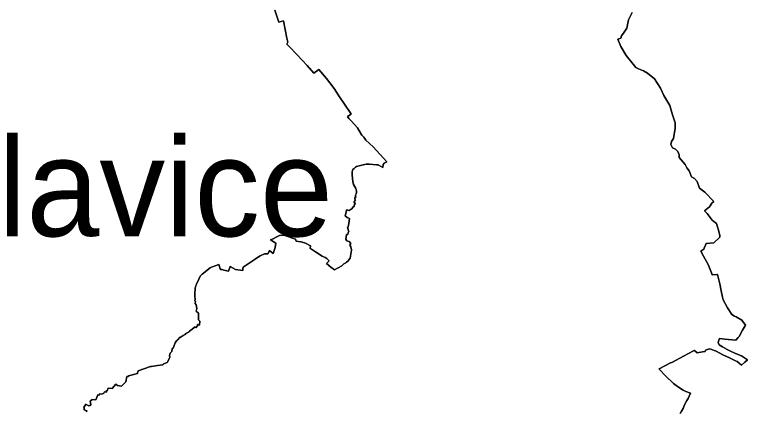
# Model space of a CAD drawing. Extents: x -742239 to -650174, y -1010569 to -945473.
# Drawn here: x -699245 to -695553, y -989972 to -987975 of the extents above; entities that cross this region are included whole.
import ezdxf

# ---------------------------------------------------------------- set-up
doc = ezdxf.new("R2010")
doc.units = 0
doc.layers.add('Hranice obcí', color=7, linetype='Continuous')
doc.layers.add('Obce popis', color=7, linetype='Continuous')

msp = doc.modelspace()

# ---------------------------------------------------------------- linework, layer by layer
at = {"layer": 'Hranice obcí'}
for points in [[(-697656, -988318.1), (-697673, -988296), (-697712.7, -988250.1), (-697736.3, -988270), (-697771.5, -988230), (-697796, -988204.3), (-697824.2, -988173.6), (-697857.1, -988139.3), (-697873.3, -988123.9), (-697868.9, -988113.7), (-697873.3, -988093.1), (-697890.4, -988005.7), (-697913.2, -988013), (-697917.6, -988002.1), (-697932.9, -987952.4)], [(-697932.9, -987952.4), (-697917.6, -988002.1), (-697913.2, -988013), (-697890.4, -988005.7), (-697873.3, -988093.1), (-697868.9, -988113.7), (-697873.3, -988123.9), (-697857.1, -988139.3), (-697824.2, -988173.6), (-697796, -988204.3), (-697771.5, -988230), (-697736.3, -988270), (-697712.7, -988250.1), (-697673, -988296), (-697656, -988318.1), (-697634.5, -988345.7), (-697611.1, -988384.2), (-697579.5, -988431.1), (-697554.7, -988467.7), (-697549.3, -988475), (-697566.8, -988488)], [(-695721.4, -989124.5), (-695692.1, -989094.4), (-695692.1, -989084.4), (-695695.8, -989068.6), (-695696.4, -989065.6), (-695704.5, -989037.3), (-695708.8, -989026.4), (-695721.4, -989016.3), (-695730.1, -989009), (-695754.6, -988975.8), (-695767.5, -988964), (-695768.3, -988963.1), (-695759.5, -988955.6), (-695743.6, -988941.9), (-695730.9, -988923.8), (-695721.3, -988915.3), (-695767.7, -988867.7), (-695793.4, -988849.2), (-695805.2, -988814.5), (-695819.4, -988798.9), (-695821.9, -988797.7), (-695833.8, -988791.6), (-695845.3, -988760.3), (-695858.3, -988745.5), (-695865.8, -988729.1), (-695896.4, -988693.9), (-695896.1, -988690.9), (-695896.8, -988679.7), (-695902.8, -988664.4), (-695914.5, -988652.8), (-695929.3, -988644.5), (-695938.4, -988629.2), (-695934.3, -988612.9), (-695924.1, -988598.2), (-695916.4, -988546), (-695916.5, -988518.9), (-695930.3, -988479), (-695943.7, -988432.1), (-695973.2, -988381.3), (-695989.6, -988345), (-696019.9, -988297.6), (-696055, -988270), (-696076, -988257.4), (-696101.4, -988247.4), (-696114.8, -988240.1), (-696128.7, -988224.4), (-696163.4, -988179.6), (-696189.7, -988135.3), (-696204.7, -988098.1), (-696190, -988093.3), (-696186, -988081.9), (-696172.6, -988062.6), (-696159.4, -988042.7), (-696152.3, -988000.5), (-696141.8, -987980.7), (-696132.8, -987964.4)], [(-696132.8, -987964.4), (-696141.8, -987980.7), (-696152.3, -988000.5), (-696159.4, -988042.7), (-696172.6, -988062.6), (-696186, -988081.9), (-696190, -988093.3), (-696204.7, -988098.1), (-696189.7, -988135.3), (-696163.4, -988179.6), (-696128.7, -988224.4), (-696114.8, -988240.1), (-696101.4, -988247.4), (-696076, -988257.4), (-696055, -988270), (-696019.9, -988297.6), (-695989.6, -988345), (-695973.2, -988381.3), (-695943.7, -988432.1), (-695930.3, -988479), (-695916.5, -988518.9), (-695916.4, -988546), (-695924.1, -988598.2), (-695934.3, -988612.9), (-695938.4, -988629.2), (-695929.3, -988644.5), (-695914.5, -988652.8), (-695902.8, -988664.4)], [(-697802.5, -989118.8), (-697800.6, -989118.9), (-697779.5, -989125.1), (-697753.7, -989138.1), (-697755.4, -989151.5), (-697749.4, -989156.4), (-697728.3, -989168.6), (-697694.4, -989190.3), (-697680.3, -989198.2), (-697671.6, -989202.9), (-697660.5, -989214.4), (-697673, -989227.8), (-697650.9, -989246.3), (-697632.3, -989259.6), (-697595.8, -989240), (-697593.2, -989235.4), (-697586.1, -989229), (-697576.5, -989224.8), (-697574.5, -989223.1), (-697572.2, -989221.3), (-697565.1, -989215.3), (-697554.4, -989201.2), (-697546.8, -989160.2), (-697547.2, -989158.3), (-697550.1, -989144.6), (-697556.4, -989135.8), (-697550.8, -989126.3), (-697558.4, -989116.6), (-697571.4, -989114.2), (-697575.1, -989105), (-697572.8, -989081), (-697566.1, -989081.2), (-697564, -989071.9), (-697561.3, -989068.7), (-697567.2, -989046.1), (-697564.3, -989045.5), (-697563.9, -989042.5), (-697561.5, -989026.2), (-697557.5, -989000.4), (-697569.6, -988996.7), (-697578.6, -988988), (-697573.2, -988962.4), (-697572.5, -988959.3), (-697572.2, -988958.2), (-697559.2, -988960.3), (-697549.5, -988954.4), (-697547.2, -988953.1), (-697545.4, -988952.3), (-697539.3, -988941.7), (-697533.3, -988939.9), (-697531.7, -988928.7), (-697527.8, -988926.1), (-697535, -988919.7), (-697527.9, -988908.8), (-697528.8, -988906.4), (-697529.9, -988901.9), (-697529.8, -988896.1), (-697526, -988896.1), (-697525.8, -988891.4), (-697527.2, -988891.1), (-697526.8, -988883.7), (-697524.4, -988877.4), (-697522.9, -988870.6), (-697522.7, -988864.3), (-697523.4, -988856.4), (-697525.2, -988850.8), (-697526.9, -988846.1), (-697537.2, -988830.7), (-697540.8, -988815.1), (-697544.2, -988782.4), (-697543.5, -988765.4), (-697542.5, -988759.6), (-697541, -988754), (-697534.6, -988748.7), (-697526.9, -988743.3), (-697521.4, -988739.5), (-697502.1, -988733.9), (-697494.8, -988732.3), (-697473, -988727.3), (-697457.4, -988726.9), (-697421.6, -988730.8), (-697412.5, -988731.7), (-697390.1, -988744.4), (-697387.8, -988729.9), (-697382.7, -988721.9), (-697369.9, -988716), (-697438, -988639.4), (-697475.7, -988606.7), (-697484.7, -988591), (-697495.2, -988582.1), (-697498.2, -988577), (-697517.3, -988544.8), (-697548.7, -988509.6), (-697560.7, -988496.7), (-697566.8, -988488), (-697549.3, -988475), (-697554.7, -988467.7), (-697579.5, -988431.1), (-697611.1, -988384.2), (-697634.5, -988345.7), (-697656, -988318.1)], [(-697566.8, -988488), (-697560.7, -988496.7), (-697548.7, -988509.6), (-697517.3, -988544.8), (-697498.2, -988577), (-697495.2, -988582.1), (-697484.7, -988591), (-697475.7, -988606.7), (-697438, -988639.4), (-697369.9, -988716), (-697382.7, -988721.9), (-697387.8, -988729.9), (-697390.1, -988744.4), (-697412.5, -988731.7), (-697421.6, -988730.8), (-697457.4, -988726.9), (-697473, -988727.3), (-697494.8, -988732.3), (-697502.1, -988733.9), (-697521.4, -988739.5), (-697526.9, -988743.3), (-697534.6, -988748.7), (-697541, -988754), (-697542.5, -988759.6), (-697543.5, -988765.4), (-697544.2, -988782.4), (-697540.8, -988815.1), (-697537.2, -988830.7), (-697526.9, -988846.1), (-697525.2, -988850.8), (-697523.4, -988856.4), (-697522.7, -988864.3), (-697522.9, -988870.6), (-697524.4, -988877.4), (-697526.8, -988883.7), (-697527.2, -988891.1), (-697525.8, -988891.4), (-697526, -988896.1), (-697529.8, -988896.1), (-697529.9, -988901.9), (-697528.8, -988906.4), (-697527.9, -988908.8), (-697535, -988919.7), (-697527.8, -988926.1), (-697531.7, -988928.7), (-697533.3, -988939.9), (-697539.3, -988941.7), (-697545.4, -988952.3), (-697547.2, -988953.1), (-697549.5, -988954.4), (-697559.2, -988960.3), (-697572.2, -988958.2), (-697572.5, -988959.3), (-697573.2, -988962.4), (-697578.6, -988988), (-697569.6, -988996.7), (-697557.5, -989000.4), (-697561.5, -989026.2), (-697563.9, -989042.5), (-697564.3, -989045.5), (-697567.2, -989046.1), (-697561.3, -989068.7), (-697564, -989071.9), (-697566.1, -989081.2), (-697572.8, -989081), (-697575.1, -989105), (-697571.4, -989114.2), (-697558.4, -989116.6), (-697550.8, -989126.3), (-697556.4, -989135.8), (-697550.1, -989144.6), (-697547.2, -989158.3), (-697546.8, -989160.2), (-697554.4, -989201.2), (-697565.1, -989215.3), (-697572.2, -989221.3), (-697574.5, -989223.1), (-697576.5, -989224.8), (-697586.1, -989229), (-697593.2, -989235.4), (-697595.8, -989240), (-697632.3, -989259.6), (-697650.9, -989246.3), (-697673, -989227.8), (-697660.5, -989214.4), (-697671.6, -989202.9), (-697680.3, -989198.2), (-697694.4, -989190.3), (-697728.3, -989168.6), (-697749.4, -989156.4), (-697755.4, -989151.5), (-697753.7, -989138.1), (-697779.5, -989125.1), (-697800.6, -989118.9), (-697802.5, -989118.8), (-697826.8, -989115.8), (-697829.2, -989105.6), (-697883.4, -989086.9), (-697889.1, -989085.1), (-697894.9, -989085.5), (-697910.2, -989086.6)], [(-695902.8, -988664.4), (-695896.8, -988679.7), (-695896.1, -988690.9), (-695896.4, -988693.9), (-695865.8, -988729.1), (-695858.3, -988745.5), (-695845.3, -988760.3), (-695833.8, -988791.6), (-695821.9, -988797.7), (-695819.4, -988798.9), (-695805.2, -988814.5), (-695793.4, -988849.2), (-695767.7, -988867.7), (-695721.3, -988915.3), (-695730.9, -988923.8), (-695743.6, -988941.9), (-695759.5, -988955.6), (-695768.3, -988963.1), (-695767.5, -988964), (-695754.6, -988975.8), (-695730.1, -989009), (-695721.4, -989016.3), (-695708.8, -989026.4), (-695704.5, -989037.3), (-695696.4, -989065.6), (-695695.8, -989068.6), (-695692.1, -989084.4), (-695692.1, -989094.4), (-695721.4, -989124.5), (-695760.7, -989127.6), (-695767.7, -989143.2), (-695768.8, -989146.3), (-695772.4, -989155.1), (-695787.7, -989165.9), (-695773.7, -989190.6), (-695749.3, -989232.9), (-695733.9, -989274.7), (-695729.6, -989284.4), (-695706.4, -989282.9), (-695702.4, -989282.4), (-695697.3, -989303.2), (-695691, -989330.7), (-695684.7, -989366), (-695677.9, -989396.7), (-695673.7, -989411.5), (-695653.4, -989451.8), (-695630.6, -989484.2), (-695616.6, -989492.3), (-695608.6, -989496.8), (-695580.3, -989513), (-695561.7, -989537.8), (-695576.7, -989564.3), (-695594.4, -989594.6), (-695597.5, -989598.8), (-695599.4, -989600.7), (-695610.1, -989614.2), (-695665.8, -989608.8), (-695693.6, -989606), (-695696.6, -989614.7), (-695700.3, -989625.4), (-695694.5, -989637.6), (-695678.4, -989647.2), (-695653.9, -989661), (-695641.4, -989667.5), (-695611.6, -989680.7), (-695582.2, -989693.5), (-695552.7, -989713.4), (-695566.1, -989724.9), (-695582.8, -989740), (-695603.3, -989720.8), (-695612.3, -989717.2), (-695629.1, -989709.1), (-695645.2, -989701.9), (-695672.8, -989688.8), (-695713.4, -989668.3), (-695719.3, -989665.7), (-695727.9, -989662.6), (-695731.9, -989661.2), (-695744.1, -989657.8), (-695764.1, -989663.7), (-695766, -989670.9), (-695778.7, -989673.4), (-695804.9, -989678.3), (-695818.4, -989665.8), (-695820, -989666.2), (-695852.1, -989682.7), (-695871.8, -989692), (-695933.1, -989725.6), (-695939.1, -989728.5), (-695996.3, -989758.8), (-695994.5, -989761.2), (-695965, -989794.3), (-695924.3, -989831.6), (-695899.3, -989851.3), (-695875.3, -989866), (-695862.2, -989872.8), (-695839.2, -989881.3), (-695850.7, -989907.7), (-695857.5, -989918.5), (-695864.8, -989930), (-695865.8, -989932.2)], [(-697910.2, -989086.6), (-697927.5, -989095.5), (-697941.3, -989104.1), (-697954.7, -989109.3), (-697929, -989125.8), (-697931.4, -989147.2), (-697941.7, -989176.8), (-697959.8, -989162.8), (-697962.8, -989167.8), (-697969.1, -989178.9), (-697971.5, -989178.7), (-697984.9, -989179.5), (-698008.3, -989189.6), (-698020.5, -989197.9), (-698037.2, -989209.3), (-698093.7, -989247), (-698094, -989248.7), (-698094.6, -989252.2), (-698095.6, -989262.5), (-698131.9, -989258.2), (-698158.6, -989242.8), (-698166.9, -989266.7), (-698189.9, -989261.7), (-698199.8, -989257.7), (-698206.9, -989258.1), (-698209.8, -989257.1), (-698209.2, -989254.1), (-698215.3, -989232.2), (-698252.8, -989245.7), (-698258.7, -989250.1), (-698299.1, -989281.1), (-698309.4, -989292), (-698316.6, -989306.6), (-698328.4, -989332.4), (-698329.6, -989335.6), (-698332.3, -989342.4), (-698333.3, -989345.6), (-698335.6, -989351.6), (-698337.2, -989381.9), (-698337.2, -989394.2), (-698335.4, -989407), (-698336.9, -989416), (-698333.6, -989419.4), (-698335.2, -989428.9), (-698329.8, -989436), (-698326.1, -989454.2), (-698330.2, -989468.1), (-698318.5, -989477.4), (-698317.6, -989511.2), (-698312.1, -989517.7), (-698313.8, -989536.4), (-698315.7, -989537.7), (-698323.5, -989534.2), (-698322.9, -989541.8), (-698331.6, -989551.6), (-698333.2, -989548.5), (-698334.7, -989547), (-698364.4, -989569), (-698365.2, -989571.6), (-698381.4, -989580), (-698385.3, -989584.9), (-698394.9, -989591), (-698410.7, -989600.1), (-698415.2, -989601.2), (-698416.9, -989606.6), (-698426.3, -989613.3), (-698429.6, -989617.5), (-698435.5, -989628), (-698445.1, -989653.4), (-698451.1, -989656.5), (-698453, -989670.3), (-698461.8, -989679.9), (-698464.3, -989691.9), (-698463.3, -989700.2), (-698473.4, -989720.5), (-698475.2, -989724), (-698476.7, -989726.8), (-698480.8, -989728.3), (-698495.6, -989734.6), (-698497.6, -989737.9), (-698524.7, -989741.1), (-698554.7, -989746.9), (-698560, -989747.3), (-698622.4, -989767.5), (-698626.2, -989778.3), (-698625.8, -989781.7), (-698671.2, -989793.7), (-698671.3, -989797.3), (-698678.6, -989797.7), (-698685, -989823), (-698706.2, -989845.3), (-698726.8, -989841.7), (-698735.5, -989835), (-698754, -989857.7), (-698773.3, -989855.6), (-698778.2, -989868.3), (-698784.1, -989869), (-698782, -989875.4), (-698792.1, -989874.5), (-698794.7, -989881.6), (-698806.2, -989885.5)], [(-698773.3, -989855.6), (-698754, -989857.7), (-698735.5, -989835), (-698726.8, -989841.7), (-698706.2, -989845.3), (-698685, -989823), (-698678.6, -989797.7), (-698671.3, -989797.3), (-698671.2, -989793.7), (-698625.8, -989781.7), (-698626.2, -989778.3), (-698622.4, -989767.5), (-698560, -989747.3), (-698554.7, -989746.9), (-698524.7, -989741.1), (-698497.6, -989737.9), (-698495.6, -989734.6), (-698480.8, -989728.3), (-698476.7, -989726.8), (-698475.2, -989724), (-698473.4, -989720.5), (-698463.3, -989700.2), (-698464.3, -989691.9), (-698461.8, -989679.9), (-698453, -989670.3), (-698451.1, -989656.5), (-698445.1, -989653.4), (-698435.5, -989628), (-698429.6, -989617.5), (-698426.3, -989613.3), (-698416.9, -989606.6), (-698415.2, -989601.2), (-698410.7, -989600.1), (-698394.9, -989591), (-698385.3, -989584.9), (-698381.4, -989580), (-698365.2, -989571.6), (-698364.4, -989569), (-698334.7, -989547), (-698333.2, -989548.5), (-698331.6, -989551.6), (-698322.9, -989541.8), (-698323.5, -989534.2), (-698315.7, -989537.7), (-698313.8, -989536.4), (-698312.1, -989517.7), (-698317.6, -989511.2), (-698318.5, -989477.4), (-698330.2, -989468.1), (-698326.1, -989454.2), (-698329.8, -989436), (-698335.2, -989428.9), (-698333.6, -989419.4), (-698336.9, -989416), (-698335.4, -989407), (-698337.2, -989394.2), (-698337.2, -989381.9), (-698335.6, -989351.6), (-698333.3, -989345.6), (-698332.3, -989342.4), (-698329.6, -989335.6), (-698328.4, -989332.4), (-698316.6, -989306.6), (-698309.4, -989292), (-698299.1, -989281.1), (-698258.7, -989250.1), (-698252.8, -989245.7), (-698215.3, -989232.2), (-698209.2, -989254.1), (-698209.8, -989257.1), (-698206.9, -989258.1), (-698199.8, -989257.7), (-698189.9, -989261.7), (-698166.9, -989266.7), (-698158.6, -989242.8), (-698131.9, -989258.2), (-698095.6, -989262.5), (-698094.6, -989252.2), (-698094, -989248.7), (-698093.7, -989247), (-698037.2, -989209.3), (-698020.5, -989197.9), (-698008.3, -989189.6), (-697984.9, -989179.5), (-697971.5, -989178.7), (-697969.1, -989178.9), (-697962.8, -989167.8), (-697959.8, -989162.8), (-697941.7, -989176.8), (-697931.4, -989147.2), (-697929, -989125.8), (-697954.7, -989109.3), (-697941.3, -989104.1), (-697927.5, -989095.5), (-697910.2, -989086.6), (-697894.9, -989085.5), (-697889.1, -989085.1), (-697883.4, -989086.9), (-697829.2, -989105.6), (-697826.8, -989115.8), (-697802.5, -989118.8)], [(-695891.6, -989983.3), (-695884.3, -989971), (-695876.7, -989958), (-695872.1, -989948.2), (-695865.8, -989932.2), (-695864.8, -989930), (-695857.5, -989918.5), (-695850.7, -989907.7), (-695839.2, -989881.3), (-695862.2, -989872.8), (-695875.3, -989866), (-695899.3, -989851.3), (-695924.3, -989831.6), (-695965, -989794.3), (-695994.5, -989761.2), (-695996.3, -989758.8), (-695939.1, -989728.5), (-695933.1, -989725.6), (-695871.8, -989692), (-695852.1, -989682.7), (-695820, -989666.2), (-695818.4, -989665.8), (-695804.9, -989678.3), (-695778.7, -989673.4), (-695766, -989670.9), (-695764.1, -989663.7), (-695744.1, -989657.8), (-695731.9, -989661.2), (-695727.9, -989662.6), (-695719.3, -989665.7), (-695713.4, -989668.3), (-695672.8, -989688.8), (-695645.2, -989701.9), (-695629.1, -989709.1), (-695612.3, -989717.2), (-695603.3, -989720.8), (-695582.8, -989740), (-695566.1, -989724.9), (-695552.7, -989713.4), (-695582.2, -989693.5), (-695611.6, -989680.7), (-695641.4, -989667.5), (-695653.9, -989661), (-695678.4, -989647.2), (-695694.5, -989637.6), (-695700.3, -989625.4), (-695696.6, -989614.7), (-695693.6, -989606), (-695665.8, -989608.8), (-695610.1, -989614.2), (-695599.4, -989600.7), (-695597.5, -989598.8), (-695594.4, -989594.6), (-695576.7, -989564.3), (-695561.7, -989537.8), (-695580.3, -989513), (-695608.6, -989496.8), (-695616.6, -989492.3), (-695630.6, -989484.2), (-695653.4, -989451.8), (-695673.7, -989411.5), (-695677.9, -989396.7), (-695684.7, -989366), (-695691, -989330.7), (-695697.3, -989303.2), (-695702.4, -989282.4), (-695706.4, -989282.9), (-695729.6, -989284.4), (-695733.9, -989274.7), (-695749.3, -989232.9), (-695773.7, -989190.6), (-695787.7, -989165.9), (-695772.4, -989155.1), (-695768.8, -989146.3), (-695767.7, -989143.2), (-695760.7, -989127.6), (-695721.4, -989124.5)], [(-698881.8, -989975.3), (-698880.1, -989969.2), (-698895.2, -989964.1), (-698894.8, -989955.8), (-698896.6, -989950.9), (-698889.4, -989943.5), (-698887.9, -989935.7), (-698870.6, -989944.4), (-698864.8, -989942.2), (-698861.4, -989937.9), (-698863.5, -989921.2), (-698853.4, -989912.3), (-698836.4, -989913.9), (-698825.4, -989889.5), (-698820.5, -989890.7), (-698815.6, -989884.6), (-698806.2, -989885.5), (-698794.7, -989881.6), (-698792.1, -989874.5), (-698782, -989875.4), (-698784.1, -989869), (-698778.2, -989868.3), (-698773.3, -989855.6)], [(-698806.2, -989885.5), (-698815.6, -989884.6), (-698820.5, -989890.7), (-698825.4, -989889.5), (-698836.4, -989913.9), (-698853.4, -989912.3), (-698863.5, -989921.2), (-698861.4, -989937.9), (-698864.8, -989942.2), (-698870.6, -989944.4), (-698887.9, -989935.7), (-698889.4, -989943.5), (-698896.6, -989950.9), (-698894.8, -989955.8), (-698895.2, -989964.1), (-698880.1, -989969.2), (-698881.8, -989975.3)], [(-695865.8, -989932.2), (-695872.1, -989948.2), (-695876.7, -989958), (-695884.3, -989971), (-695891.6, -989983.3)]]:
    msp.add_lwpolyline(points, dxfattribs=at)

# ---------------------------------------------------------------- texts
at = {"layer": 'Obce popis'}
msp.add_text('Hlavice', height=495, dxfattribs=at).set_placement((-699810.7, -989090.4))

doc.saveas('drawing.dxf')
